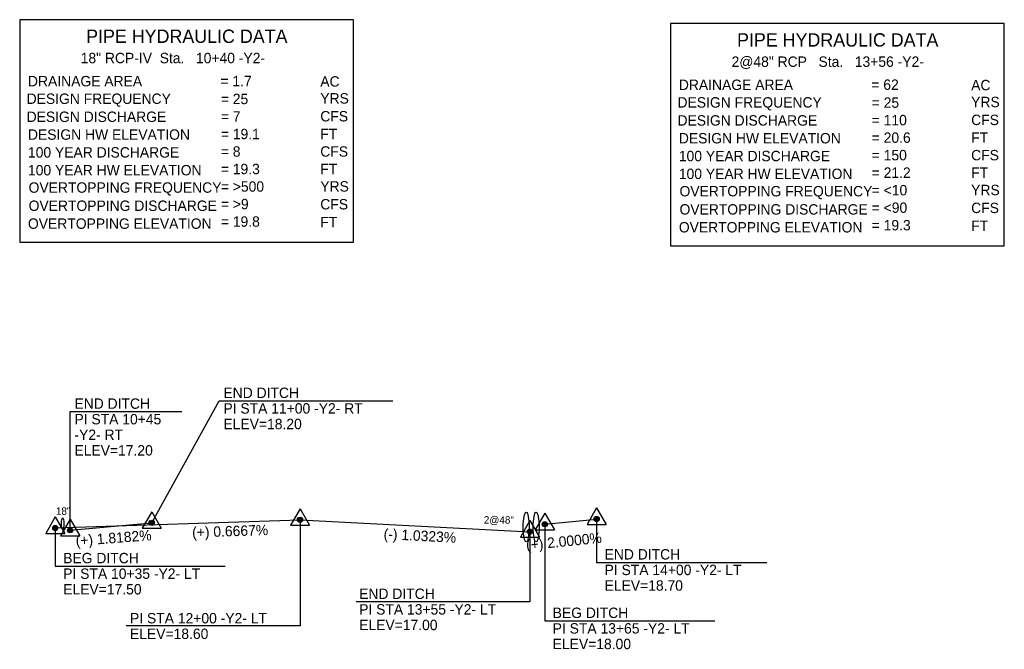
# Model space of a CAD drawing. Extents: x 2179808 to 2190174, y 63168 to 78602.
# Drawn here: x 2179952 to 2180616, y 69163 to 69587 of the extents above; entities that cross this region are included whole.
import ezdxf

# ---------------------------------------------------------------- set-up
doc = ezdxf.new("R2010")
doc.units = 0
for name, color, linetype in [('Default', 7, 'Continuous'), ('Prop Grid Mask', 7, 'Continuous'), ('Prop PFL Cross Pipe CELL', 7, 'Continuous'), ('Prop PFL Cross Pipe Text CELL', 7, 'Continuous'), ('Prop PFL Pipe Hydraulic Data CELL', 7, 'Continuous'), ('Prop Vertical Profile Ditch Grade Left', 7, 'Continuous'), ('Prop Vertical Profile Ditch Grade Left Label', 7, 'Continuous'), ('Prop Vertical Profile Ditch Grade Right', 7, 'Continuous'), ('Prop Vertical Profile Ditch Grade Right Label', 7, 'Continuous'), ('Prop VPI Ditch Grade Left Label', 7, 'Continuous'), ('Prop VPI Ditch Grade Right Label', 7, 'Continuous')]:
    doc.layers.add(name, color=color, linetype=linetype)

msp = doc.modelspace()

# ---------------------------------------------------------------- linework, layer by layer
at = {"layer": 'Default'}
for p, q in [((2180340.9, 69258.26), (2180334.45, 69247.06)), ((2180340.9, 69258.26), (2180347.4, 69247.06)), ((2179975.9, 69252.26), (2179969.45, 69241.06)), ((2179975.9, 69252.26), (2179982.4, 69241.06)), ((2180040.9, 69255.76), (2180034.45, 69244.56)), ((2180040.9, 69255.76), (2180047.4, 69244.56)), ((2180140.9, 69257.76), (2180134.45, 69246.56)), ((2180140.9, 69257.76), (2180147.4, 69246.56)), ((2180305.9, 69254.76), (2180299.45, 69243.56)), ((2180305.9, 69254.76), (2180312.4, 69243.56)), ((2179985.9, 69250.76), (2179979.45, 69239.56)), ((2179985.9, 69250.76), (2179992.4, 69239.56)), ((2180134.45, 69246.56), (2180147.4, 69246.56)), ((2180295.9, 69249.76), (2180289.45, 69238.56)), ((2180295.9, 69249.76), (2180302.4, 69238.56)), ((2180334.45, 69247.06), (2180347.4, 69247.06)), ((2179969.45, 69241.06), (2179982.4, 69241.06)), ((2179979.45, 69239.56), (2179992.4, 69239.56)), ((2180034.45, 69244.56), (2180047.4, 69244.56)), ((2180289.45, 69238.56), (2180302.4, 69238.56)), ((2180299.45, 69243.56), (2180312.4, 69243.56))]:
    msp.add_line(p, q, dxfattribs=at)
for centre, radius in [((2180140.9, 69250.28), 1.75), ((2180140.9, 69250.28), 1.2), ((2180340.9, 69250.78), 1.75), ((2180340.9, 69250.78), 1.2), ((2179975.9, 69244.78), 1.75), ((2179975.9, 69244.78), 1.2), ((2179985.9, 69243.28), 1.75), ((2180040.9, 69248.28), 1.75), ((2180040.9, 69248.28), 1.2), ((2180305.9, 69247.28), 1.75), ((2180305.9, 69247.28), 1.2), ((2179985.9, 69243.28), 1.2), ((2180295.9, 69242.28), 1.75), ((2180295.9, 69242.28), 1.2)]:
    msp.add_circle(centre, radius, dxfattribs=at)
at = {"layer": 'Prop Grid Mask'}
for points in [[(2179951.91, 69437.26), (2180176.91, 69437.26), (2180176.91, 69587.26), (2179951.91, 69587.26)], [(2180390.75, 69434.8), (2180615.75, 69434.8), (2180615.75, 69584.8), (2180390.75, 69584.8)]]:
    msp.add_lwpolyline(points, close=True, dxfattribs=at)
at = {"layer": 'Prop PFL Cross Pipe CELL'}
for centre, major_axis in [((2179980.9, 69247.77), (0, 3.75)), ((2180293.4, 69245.38), (0, 10)), ((2180300.1, 69245.38), (0, 10))]:
    msp.add_ellipse(centre, major_axis=major_axis, ratio=0.2, dxfattribs=at)
at = {"layer": 'Prop Vertical Profile Ditch Grade Left'}
msp.add_line((2180305.9, 69247.28), (2180340.9, 69250.78), dxfattribs=at)
msp.add_lwpolyline([(2179975.9, 69244.78), (2180140.9, 69250.28), (2180295.9, 69242.28)], dxfattribs=at)
at = {"layer": 'Prop Vertical Profile Ditch Grade Right'}
msp.add_line((2179985.9, 69243.28), (2180040.9, 69248.28), dxfattribs=at)
at = {"layer": 'Prop VPI Ditch Grade Left Label'}
for points in [[(2179975.9, 69244.78), (2179975.9, 69218.99), (2180090.53, 69218.99)], [(2180140.9, 69250.28), (2180140.9, 69178.92), (2180023.74, 69178.92)], [(2180305.9, 69247.28), (2180305.9, 69182.12), (2180420.53, 69182.12)], [(2180340.9, 69250.78), (2180340.9, 69221.51), (2180455.53, 69221.51)], [(2180295.9, 69242.28), (2180295.9, 69195.1), (2180178.74, 69195.1)]]:
    msp.add_lwpolyline(points, dxfattribs=at)
for centre in [(2180340.9, 69250.78), (2179975.9, 69244.78), (2180140.9, 69250.28), (2180305.9, 69247.28), (2180295.9, 69242.28)]:
    msp.add_circle(centre, 0.5, dxfattribs=at)
at = {"layer": 'Prop VPI Ditch Grade Right Label'}
for points in [[(2180040.9, 69248.28), (2180086.35, 69330.55), (2180203.57, 69330.55)], [(2179985.9, 69243.28), (2179985.9, 69323.28), (2180061.32, 69323.28)]]:
    msp.add_lwpolyline(points, dxfattribs=at)
for centre in [(2180040.9, 69248.28), (2179985.9, 69243.28)]:
    msp.add_circle(centre, 0.5, dxfattribs=at)

# ---------------------------------------------------------------- texts
at = {"layer": 'Prop PFL Cross Pipe Text CELL'}
for s, p in [('18"', (2179976.31, 69253.63)), ('2@48"', (2180264.82, 69247.7))]:
    msp.add_text(s, height=5, dxfattribs=at).set_placement(p)
at = {"layer": 'Prop PFL Pipe Hydraulic Data CELL'}
for s, height, p in [('PIPE HYDRAULIC DATA', 8.9997, (2179996.71, 69571.61)), ('PIPE HYDRAULIC DATA', 8.9997, (2180435.55, 69569.15)), (' 18" RCP-IV  Sta.   10+40 -Y2-', 6.9996, (2179990.45, 69557.94)), (' 2@48" RCP   Sta.   13+56 -Y2-', 6.9996, (2180429.28, 69555.48)), ('DRAINAGE AREA', 6.9999, (2179957.49, 69542.36)), ('= 1.7    ', 7, (2180087.28, 69542.44)), ('AC', 7, (2180154.58, 69542.16)), ('DRAINAGE AREA', 6.9999, (2180396.32, 69539.9)), ('= 62     ', 7, (2180526.11, 69539.98)), ('AC', 7, (2180593.41, 69539.7)), ('DESIGN FREQUENCY', 6.9999, (2179956.59, 69530.51)), ('= 25 ', 7, (2180087.52, 69530.36)), ('YRS', 7, (2180154.58, 69530.76)), ('DESIGN FREQUENCY', 6.9999, (2180395.42, 69528.05)), ('= 25 ', 7, (2180526.35, 69527.9)), ('YRS', 7, (2180593.41, 69528.3)), ('DESIGN DISCHARGE', 6.9999, (2179956.59, 69518.36)), ('= 7       ', 7, (2180087.52, 69518.56)), ('CFS', 7, (2180154.58, 69518.71)), ('DESIGN DISCHARGE', 6.9999, (2180395.42, 69515.9)), ('= 110     ', 7, (2180526.35, 69516.1)), ('CFS', 7, (2180593.41, 69516.25)), ('DESIGN HW ELEVATION', 6.9999, (2179957.49, 69506.36)), ('= 19.1    ', 7, (2180087.52, 69506.76)), ('FT', 7, (2180154.58, 69506.76)), ('DESIGN HW ELEVATION', 6.9999, (2180396.32, 69503.9)), ('= 20.6    ', 7, (2180526.35, 69504.3)), ('FT', 7, (2180593.41, 69504.3)), ('100 YEAR DISCHARGE', 6.9999, (2179957.49, 69494.36)), ('= 8       ', 7, (2180087.52, 69494.96)), ('CFS', 7, (2180154.58, 69494.96)), ('100 YEAR DISCHARGE', 6.9999, (2180396.32, 69491.9)), ('= 150     ', 7, (2180526.35, 69492.5)), ('CFS', 7, (2180593.41, 69492.5)), ('= 19.3    ', 7, (2180087.52, 69483.16)), ('100 YEAR HW ELEVATION', 6.9999, (2179957.49, 69482.36)), ('FT', 7, (2180154.58, 69483.16)), ('100 YEAR HW ELEVATION', 6.9999, (2180396.32, 69479.9)), ('= 21.2    ', 7, (2180526.35, 69480.7)), ('FT', 7, (2180593.41, 69480.7)), ('OVERTOPPING FREQUENCY', 6.9999, (2179957.94, 69470.66)), ('= >500', 7, (2180087.52, 69471.36)), ('YRS', 7, (2180154.58, 69471.46)), ('OVERTOPPING FREQUENCY', 6.9999, (2180396.77, 69468.2)), ('= <10', 7, (2180526.35, 69468.9)), ('YRS', 7, (2180593.41, 69469)), ('OVERTOPPING DISCHARGE', 6.9999, (2179957.94, 69458.41)), ('= >9      ', 7, (2180087.52, 69459.56)), ('CFS', 7, (2180154.58, 69459.41)), ('= <90     ', 7, (2180526.35, 69457.1)), ('CFS', 7, (2180593.41, 69456.95)), ('OVERTOPPING DISCHARGE', 6.9999, (2180396.77, 69455.95)), ('OVERTOPPING ELEVATION', 6.9999, (2179957.49, 69446.36)), ('= 19.8    ', 7, (2180087.52, 69447.76)), ('FT', 7, (2180154.58, 69447.36)), ('OVERTOPPING ELEVATION', 6.9999, (2180396.32, 69443.9)), ('= 19.3    ', 7, (2180526.35, 69445.3)), ('FT', 7, (2180593.41, 69444.9))]:
    msp.add_text(s, height=height, dxfattribs=at).set_placement(p)
at = {"layer": 'Prop Vertical Profile Ditch Grade Left Label'}
for s, rotation, p in [('(+) 0.6667%', 1.90915, (2180068.29, 69238.32)), ('(-) 1.0323%', 357.04542, (2180197.14, 69237.32)), ('(+) 2.0000%', 5.71059, (2180293.65, 69229.72))]:
    msp.add_text(s, height=7, rotation=rotation, dxfattribs=at).set_placement(p)
at = {"layer": 'Prop Vertical Profile Ditch Grade Right Label'}
msp.add_text('(+) 1.8182%', height=7, rotation=4.39871, dxfattribs=at).set_placement((2179989.93, 69232.62))
at = {"layer": 'Prop VPI Ditch Grade Left Label'}
for s, p in [('BEG DITCH', (2179981.25, 69220.99)), ('END DITCH', (2180346.25, 69223.51)), ('PI STA 14+00 -Y2- LT', (2180346.25, 69213.01)), ('PI STA 10+35 -Y2- LT', (2179981.25, 69210.49)), ('ELEV=17.50', (2179981.25, 69199.99)), ('ELEV=18.70', (2180346.25, 69202.51)), ('END DITCH', (2180180.79, 69196.93)), ('PI STA 13+55 -Y2- LT', (2180180.79, 69186.43)), ('PI STA 12+00 -Y2- LT', (2180026.28, 69180.47)), ('BEG DITCH', (2180311.25, 69184.12)), ('ELEV=17.00', (2180180.79, 69175.93)), ('PI STA 13+65 -Y2- LT', (2180311.25, 69173.62)), ('ELEV=18.60', (2180026.28, 69169.97)), ('ELEV=18.00', (2180311.25, 69163.12))]:
    msp.add_text(s, height=7, dxfattribs=at).set_placement(p)
at = {"layer": 'Prop VPI Ditch Grade Right Label'}
for s, p in [('END DITCH', (2180089.27, 69332.35)), ('PI STA 11+00 -Y2- RT', (2180089.27, 69321.85)), ('ELEV=18.20', (2180089.27, 69311.35))]:
    msp.add_text(s, height=7, rotation=360, dxfattribs=at).set_placement(p)
for s, p in [('END DITCH', (2179988.83, 69325.08)), ('PI STA 10+45', (2179988.83, 69314.58)), ('-Y2- RT', (2179988.83, 69304.08)), ('ELEV=17.20', (2179988.83, 69293.58))]:
    msp.add_text(s, height=7, dxfattribs=at).set_placement(p)

doc.saveas('drawing.dxf')
